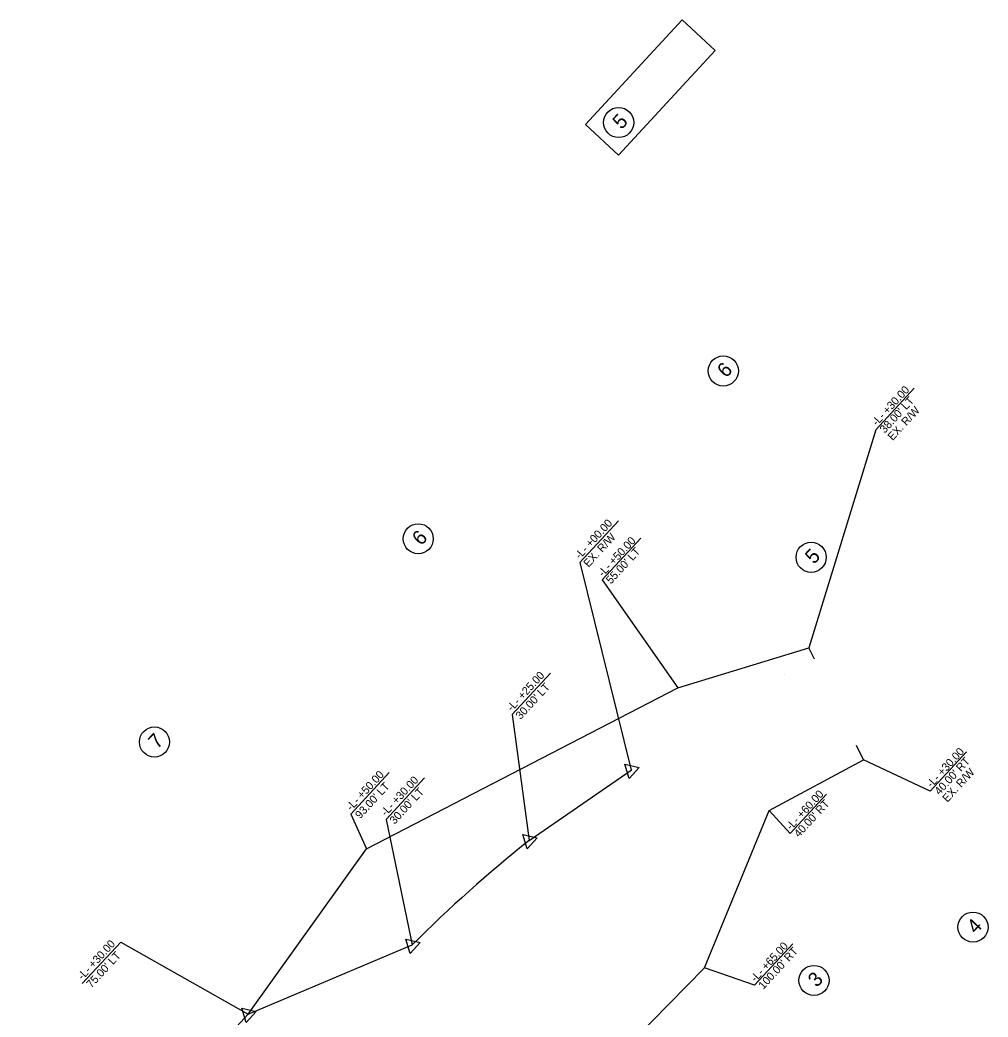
# Model space of a CAD drawing. Extents: x 1768436 to 1770837, y 999770 to 1004574.
# Drawn here: x 1768853 to 1769458, y 1000379 to 1001002 of the extents above; entities that cross this region are included whole.
import ezdxf

# ---------------------------------------------------------------- set-up
doc = ezdxf.new("R2010")
doc.units = 0
for name, color, linetype in [('Coir Fiber Wattle with PAM CG CELL', 7, 'Continuous'), ('Label A CG CELL', 7, 'Continuous'), ('Rock Inlet Sediment Trap Type C CG CELL', 7, 'Continuous'), ('Rock Pipe Inlet Sediment Trap Type A CG CELL', 7, 'Continuous'), ('Rock Pipe Inlet Sediment Trap Type B CG CELL', 7, 'Continuous'), ('Rock Pipe Inlet Sediment Trap Type B Final CELL', 7, 'Continuous'), ('Rock Silt Check Type A CG CELL', 7, 'Continuous'), ('Scratch_Level_3', 7, 'Continuous'), ('Scratch_Level_5', 7, 'Continuous')]:
    doc.layers.add(name, color=color, linetype=linetype)

msp = doc.modelspace()

# ---------------------------------------------------------------- linework, layer by layer
at = {"layer": 'Label A CG CELL'}
msp.add_lwpolyline([(1769206.91, 1000936.84), (1769267.27, 1001002.13), (1769287.96, 1000983.01), (1769227.6, 1000917.71)], close=True, dxfattribs=at)
for centre in [(1769227.61, 1000938.02), (1769292.98, 1000782.75), (1769102.37, 1000677.88), (1768937.54, 1000550.86), (1769449.01, 1000435.17), (1769349.65, 1000401.83)]:
    msp.add_circle(centre, 9.41, dxfattribs=at)
at = {"layer": 'Rock Inlet Sediment Trap Type C CG CELL'}
for p, q in [((1769203.41, 1000663.1), (1769227.44, 1000689.09)), ((1769203.41, 1000663.1), (1769235.35, 1000533.25)), ((1769160.97, 1000567.97), (1769185, 1000593.97)), ((1769160.97, 1000567.97), (1769171.62, 1000489.39)), ((1769082.25, 1000502.51), (1769106.28, 1000528.51)), ((1769082.25, 1000502.51), (1769098.49, 1000424.03)), ((1768892.41, 1000399.85), (1768916.44, 1000425.85)), ((1768916.44, 1000425.85), (1768996.04, 1000380.8))]:
    msp.add_line(p, q, dxfattribs=at)
at = {"layer": 'Rock Pipe Inlet Sediment Trap Type A CG CELL'}
for p, q in [((1769235.35, 1000533.25), (1769235.35, 1000533.25)), ((1769171.62, 1000489.39), (1769171.62, 1000489.39)), ((1769098.49, 1000424.03), (1769098.49, 1000424.03)), ((1768996.04, 1000380.8), (1768996.04, 1000380.8))]:
    msp.add_line(p, q, dxfattribs=at)
for points in [[(1769234.15, 1000527.98), (1769231.39, 1000536.92), (1769240.52, 1000534.86)], [(1769170.42, 1000484.11), (1769167.66, 1000493.05), (1769176.78, 1000490.99)], [(1769097.29, 1000418.76), (1769094.53, 1000427.7), (1769103.66, 1000425.64)], [(1768994.84, 1000375.53), (1768992.08, 1000384.47), (1769001.2, 1000382.41)]]:
    msp.add_lwpolyline(points, close=True, dxfattribs=at)
for centre in [(1769235.35, 1000533.25), (1769171.62, 1000489.39), (1769098.49, 1000424.03), (1768996.04, 1000380.8)]:
    msp.add_circle(centre, 0.112, dxfattribs=at)
at = {"layer": 'Rock Pipe Inlet Sediment Trap Type B CG CELL'}
for p, q in [((1769388.2, 1000745.91), (1769412.23, 1000771.91)), ((1769388.2, 1000745.91), (1769346.52, 1000609.77)), ((1769217.38, 1000652.24), (1769241.41, 1000678.23)), ((1769217.38, 1000652.24), (1769264.55, 1000584.62)), ((1769422.26, 1000520.14), (1769445, 1000544.76)), ((1769422.26, 1000520.14), (1769380.67, 1000539.64)), ((1769060.23, 1000505.73), (1769084.26, 1000531.72)), ((1769334.77, 1000493.74), (1769357.52, 1000518.35)), ((1769060.23, 1000505.73), (1769069.94, 1000484.11)), ((1769334.77, 1000493.74), (1769321.68, 1000508.06)), ((1769312.57, 1000398.82), (1769336.5, 1000424.71)), ((1769312.57, 1000398.82), (1769281.34, 1000409.81))]:
    msp.add_line(p, q, dxfattribs=at)
at = {"layer": 'Rock Pipe Inlet Sediment Trap Type B Final CELL'}
msp.add_circle((1769347.88, 1000666.29), 9.41, dxfattribs=at)
at = {"layer": 'Rock Silt Check Type A CG CELL'}
for p, q in [((1769331.31, 1000593.2), (1769331.33, 1000593.15)), ((1769171.62, 1000489.39), (1769235.35, 1000533.25)), ((1768996.04, 1000380.8), (1769098.49, 1000424.03)), ((1768853.49, 1000226.59), (1768996.04, 1000380.8))]:
    msp.add_line(p, q, dxfattribs=at)
msp.add_arc((1769763.92, 999753.04), 945, 128.81245, 134.7612, dxfattribs=at)
at = {"layer": 'Scratch_Level_5'}
for p, q in [((1769264.55, 1000584.62), (1769346.52, 1000609.77)), ((1769350.02, 1000602.58), (1769346.52, 1000609.77)), ((1769069.94, 1000484.11), (1769264.55, 1000584.62)), ((1769380.67, 1000539.64), (1769376.29, 1000548.63)), ((1769321.68, 1000508.06), (1769380.67, 1000539.64)), ((1769281.34, 1000409.81), (1769321.68, 1000508.06)), ((1768996.04, 1000380.8), (1769069.94, 1000484.11)), ((1769209.7, 1000336.88), (1769281.34, 1000409.81))]:
    msp.add_line(p, q, dxfattribs=at)

# ---------------------------------------------------------------- texts
at = {"layer": 'Coir Fiber Wattle with PAM CG CELL'}
for s, p in [('5', (1769229.38, 1000933.29)), ('6', (1769294.75, 1000778.01)), ('6', (1769104.14, 1000673.14)), ('7', (1768939.31, 1000546.12)), ('4', (1769450.78, 1000430.43)), ('3', (1769351.43, 1000397.09))]:
    msp.add_text(s, height=9, rotation=46.64664, dxfattribs=at).set_placement(p)
at = {"layer": 'Rock Inlet Sediment Trap Type C CG CELL'}
for s, p in [('-L- +00.00', (1769203.25, 1000664.76)), ('EX. R/W', (1769208.76, 1000659.67)), ('-L- +25.00', (1769160.81, 1000569.64)), ("30.00' LT", (1769166.32, 1000564.55)), ('-L- +30.00', (1769082.1, 1000504.18)), ("30.00' LT", (1769087.6, 1000499.09)), ('-L- +30.00', (1768892.61, 1000401.82)), ("75.00' LT", (1768898.12, 1000396.73))]:
    msp.add_text(s, height=5, rotation=47.25123, dxfattribs=at).set_placement(p)
at = {"layer": 'Rock Pipe Inlet Sediment Trap Type B CG CELL'}
for s, p in [('-L- +30.00', (1769388.88, 1000748.06)), ("38.00' LT", (1769393.84, 1000743.48)), ('EX. R/W', (1769398.79, 1000738.9)), ('-L- +50.00', (1769217.81, 1000653.81)), ("55.00' LT", (1769222.77, 1000649.23)), ('-L- +30.00', (1769423.1, 1000521.97)), ("40.00' RT", (1769428.05, 1000517.38)), ('-L- +50.00', (1769060.54, 1000507.59)), ('EX. R/W', (1769433.01, 1000512.8)), ("93.00' LT", (1769066.05, 1000502.5)), ('-L- +60.00', (1769335.28, 1000495.43)), ("40.00' RT", (1769340.23, 1000490.85)), ('-L- +65.00', (1769313.07, 1000400.5)), ("100.00' RT", (1769318.03, 1000395.92))]:
    msp.add_text(s, height=5, rotation=47.25123, dxfattribs=at).set_placement(p)
at = {"layer": 'Scratch_Level_3'}
msp.add_text('5', height=9, rotation=46.64664, dxfattribs=at).set_placement((1769349.65, 1000661.55))

doc.saveas('drawing.dxf')
